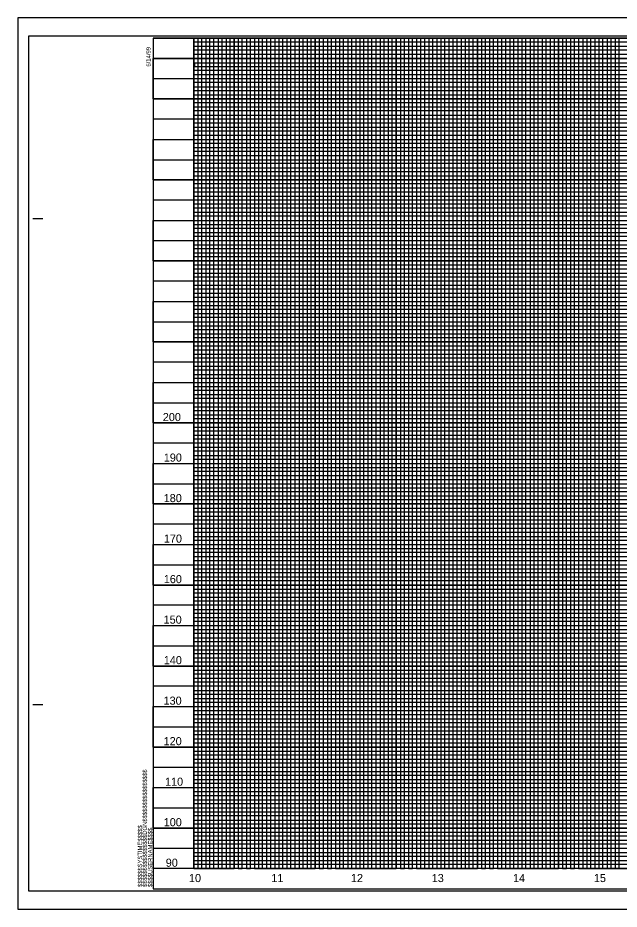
# Model space of a CAD drawing. Extents: x 1728093 to 1729777, y 538013 to 539113.
# Drawn here: x 1728093 to 1728835, y 538013 to 539113 of the extents above; entities that cross this region are included whole.
import ezdxf

# ---------------------------------------------------------------- set-up
doc = ezdxf.new("R2010")
doc.units = 0
for name, color, linetype in [('Exist Vertical Profile Horizontal Axis Label Minor', 7, 'Continuous'), ('Exist Vertical Profile Vertical Axis Label', 7, 'Continuous'), ('Scratch_Level_0', 7, 'Continuous'), ('Sheet Cutting Line CELL', 7, 'Continuous'), ('Sheet DOT Grid CELL', 7, 'Continuous'), ('Sheet Plot Border Inside CELL', 7, 'Continuous'), ('Sheet Plot Border Outside CELL', 7, 'Continuous'), ('Sheet Profile CELL', 7, 'Continuous'), ('Sheet Profile Grid Major CELL', 7, 'Continuous'), ('Sheet Profile Grid Middle CELL', 7, 'Continuous'), ('Sheet Profile Grid Minor CELL', 7, 'Continuous')]:
    doc.layers.add(name, color=color, linetype=linetype)

msp = doc.modelspace()

# ---------------------------------------------------------------- linework, layer by layer
at = {"layer": 'Scratch_Level_0'}
msp.add_lwpolyline([(1728309.9, 539088), (1729709.9, 539088), (1729709.9, 538063), (1728309.9, 538063)], close=True, dxfattribs=at)
at = {"layer": 'Sheet Cutting Line CELL'}
for p, q in [((1729776.9, 539113), (1728092.9, 539113)), ((1728092.9, 539113), (1728092.9, 538013)), ((1728092.9, 538013), (1729776.9, 538013))]:
    msp.add_line(p, q, dxfattribs=at)
at = {"layer": 'Sheet DOT Grid CELL'}
for p, q in [((1728309.9, 539088), (1728309.9, 538063)), ((1728359.9, 539088), (1728359.9, 538063)), ((1728409.9, 539088), (1728409.9, 538063)), ((1728459.9, 539088), (1728459.9, 538063)), ((1728509.9, 539088), (1728509.9, 538063)), ((1728559.9, 539088), (1728559.9, 538063)), ((1728609.9, 539088), (1728609.9, 538063)), ((1728659.9, 539088), (1728659.9, 538063)), ((1728709.9, 539088), (1728709.9, 538063)), ((1728759.9, 539088), (1728759.9, 538063)), ((1728809.9, 539088), (1728809.9, 538063)), ((1728259.9, 539063), (1729559.8, 539063)), ((1728259.9, 539013), (1729559.8, 539013)), ((1728259.9, 538963), (1729559.8, 538963)), ((1728259.9, 538913), (1729759.9, 538913)), ((1728259.9, 538863), (1729759.9, 538863)), ((1728259.9, 538813), (1729759.9, 538813)), ((1728259.9, 538763), (1729759.9, 538763)), ((1728259.9, 538713), (1729759.9, 538713)), ((1728259.9, 538613), (1729759.9, 538613)), ((1728259.9, 538563), (1729759.9, 538563)), ((1728259.9, 538513), (1729759.9, 538513)), ((1728259.9, 538463), (1729759.9, 538463)), ((1728259.9, 538413), (1729759.9, 538413)), ((1728259.9, 538363), (1729759.9, 538363)), ((1728259.9, 538313), (1729759.9, 538313)), ((1728259.9, 538263), (1729759.9, 538263)), ((1728259.9, 538213), (1729759.9, 538213)), ((1728259.9, 538163), (1729759.9, 538163)), ((1728259.9, 538113), (1729759.9, 538113))]:
    msp.add_line(p, q, dxfattribs=at)
at = {"layer": 'Sheet Plot Border Inside CELL'}
msp.add_lwpolyline([(1729772.4, 539090.5), (1728105.9, 539090.5), (1728105.9, 538035.4), (1729772.4, 538035.4)], close=True, dxfattribs=at)
at = {"layer": 'Sheet Plot Border Outside CELL'}
msp.add_lwpolyline([(1729776.9, 539113), (1728092.9, 539113), (1728092.9, 538013), (1729776.9, 538013)], close=True, dxfattribs=at)
at = {"layer": 'Sheet Profile CELL'}
for p, q in [((1728111.4, 538865.5), (1728123.9, 538865.5)), ((1728111.4, 538265.5), (1728123.9, 538265.5)), ((1729759.9, 538063), (1728259.9, 538063)), ((1728259.9, 538038), (1728259.9, 538038)), ((1728259.9, 538038), (1728259.9, 538038)), ((1728259.9, 538038), (1728259.9, 538038)), ((1728259.9, 538038), (1728259.9, 538038)), ((1728259.9, 538038), (1728259.9, 538038)), ((1728259.9, 538038), (1728259.9, 538038))]:
    msp.add_line(p, q, dxfattribs=at)
msp.add_lwpolyline([(1729759.9, 539088), (1728259.9, 539088), (1728259.9, 538038), (1729759.9, 538038)], close=True, dxfattribs=at)
msp.add_lwpolyline([(1728297.4, 538038), (1728297.4, 538038)], dxfattribs=at)
at = {"layer": 'Sheet Profile Grid Major CELL'}
for points in [[(1728259.9, 539088), (1728309.9, 539088), (1728309.9, 538063), (1728359.9, 538063), (1728359.9, 539088), (1728409.9, 539088), (1728409.9, 538063), (1728459.9, 538063), (1728459.9, 539088), (1728509.9, 539088), (1728509.9, 538063), (1728559.9, 538063), (1728559.9, 539088), (1728609.9, 539088), (1728609.9, 538063), (1728659.9, 538063), (1728659.9, 539088), (1728709.9, 539088), (1728709.9, 538063), (1728759.9, 538063), (1728759.9, 539088), (1728809.9, 539088), (1728809.9, 538063), (1728859.9, 538063)], [(1729559.8, 539013), (1728260, 539013), (1728260, 539062.9), (1729559.8, 539062.9)], [(1729759.9, 538913), (1728259.9, 538913), (1728259.9, 538963), (1729559.8, 538963)], [(1729759.9, 538813), (1728259.9, 538813), (1728259.9, 538863), (1729759.9, 538863)], [(1729759.9, 538713), (1728259.9, 538713), (1728259.9, 538763), (1729759.9, 538763)], [(1729759.9, 538613), (1728259.9, 538613), (1728259.9, 538663), (1729759.9, 538663)], [(1729759.9, 538513), (1728259.9, 538513), (1728259.9, 538563), (1729759.9, 538563)], [(1729759.9, 538413), (1728259.9, 538413), (1728259.9, 538463), (1729759.9, 538463)], [(1729759.9, 538313), (1728259.9, 538313), (1728259.9, 538363), (1729759.9, 538363)], [(1729759.9, 538213), (1728259.9, 538213), (1728259.9, 538263), (1729759.9, 538263)], [(1729759.9, 538113), (1728259.9, 538113), (1728259.9, 538163), (1729759.9, 538163)]]:
    msp.add_lwpolyline(points, dxfattribs=at)
at = {"layer": 'Sheet Profile Grid Middle CELL'}
for points in [[(1728334.9, 538063), (1728334.9, 539088), (1728384.9, 539088), (1728384.9, 538063), (1728434.9, 538063), (1728434.9, 539088), (1728484.9, 539088), (1728484.9, 538063), (1728534.9, 538063), (1728534.9, 539088), (1728584.9, 539088), (1728584.9, 538063), (1728634.9, 538063), (1728634.9, 539088), (1728684.9, 539088), (1728684.9, 538063), (1728734.9, 538063), (1728734.9, 539088), (1728784.9, 539088), (1728784.9, 538063), (1728834.9, 538063), (1728834.9, 539088), (1728884.9, 539088)], [(1728259.9, 539038), (1729559.8, 539038)], [(1729559.8, 538988), (1728259.9, 538988), (1728259.9, 538937.9), (1729559.8, 538937.9)], [(1729599.9, 538888), (1728259.9, 538888), (1728259.9, 538838), (1729759.9, 538838)], [(1729759.9, 538788), (1728259.9, 538788), (1728259.9, 538738), (1729759.9, 538738)], [(1729759.9, 538688), (1728259.9, 538688), (1728259.9, 538638), (1729759.9, 538638)], [(1729759.9, 538588), (1728259.9, 538588), (1728259.9, 538538), (1729759.9, 538538)], [(1729759.9, 538488), (1728259.9, 538488), (1728259.9, 538438), (1729759.9, 538438)], [(1729759.9, 538388), (1728259.9, 538388), (1728259.9, 538338), (1729759.9, 538338)], [(1729759.9, 538288), (1728259.9, 538288), (1728259.9, 538238), (1729759.9, 538238)], [(1729759.9, 538188), (1728259.9, 538188), (1728259.9, 538138), (1729759.9, 538138)], [(1729759.9, 538088), (1728259.9, 538088)]]:
    msp.add_lwpolyline(points, dxfattribs=at)
at = {"layer": 'Sheet Profile Grid Minor CELL'}
for p, q in [((1729709.9, 538923), (1728309.9, 538923)), ((1728309.9, 538923), (1728309.9, 538918)), ((1728309.9, 538918), (1729709.9, 538918)), ((1729709.9, 538908), (1728309.9, 538908)), ((1728309.9, 538908), (1728309.9, 538903)), ((1728309.9, 538903), (1729599.9, 538903)), ((1729599.9, 538883), (1728309.9, 538883)), ((1729709.9, 538853), (1728309.9, 538853)), ((1728309.9, 538853), (1728309.9, 538848)), ((1728309.9, 538848), (1729709.9, 538848))]:
    msp.add_line(p, q, dxfattribs=at)
for points in [[(1728314.9, 539088), (1728319.9, 539088), (1728324.9, 539088), (1728329.9, 539088), (1728339.9, 539088), (1728306.8, 539088), (1728311.8, 539088), (1728269.9, 539088), (1728274.9, 539088), (1728279.9, 539088), (1728289.9, 539088), (1728294.9, 539088), (1728299.9, 539088), (1728304.9, 539088), (1728314.9, 539088), (1728314.9, 538063), (1728319.9, 538063), (1728319.9, 539088), (1728324.9, 539088), (1728324.9, 538063), (1728329.9, 538063), (1728329.9, 539088), (1728339.9, 539088), (1728339.9, 538063), (1728344.9, 538063), (1728344.9, 539088), (1728349.9, 539088), (1728349.9, 538063), (1728354.9, 538063), (1728354.9, 539088), (1728364.9, 539088), (1728364.9, 538063), (1728369.9, 538063), (1728369.9, 539088), (1728374.9, 539088), (1728374.9, 538063), (1728379.9, 538063), (1728379.9, 539088), (1728389.9, 539088), (1728389.9, 538063), (1728394.9, 538063), (1728394.9, 539088), (1728399.9, 539088), (1728399.9, 538063), (1728404.9, 538063), (1728404.9, 539088), (1728414.9, 539088), (1728414.9, 538063), (1728419.9, 538063), (1728419.9, 539088), (1728424.9, 539088), (1728424.9, 538063), (1728429.9, 538063), (1728429.9, 539088), (1728439.9, 539088), (1728439.9, 538063), (1728444.9, 538063), (1728444.9, 539088), (1728449.9, 539088), (1728449.9, 538063), (1728454.9, 538063), (1728454.9, 539088), (1728464.9, 539088), (1728464.9, 538063), (1728469.9, 538063), (1728469.9, 539088), (1728474.9, 539088), (1728474.9, 538063)], [(1729559.8, 539083), (1728309.9, 539083), (1728309.9, 539078), (1729559.8, 539078)], [(1728474.9, 538063), (1728479.9, 538063), (1728479.9, 539088), (1728489.9, 539088), (1728489.9, 538063), (1728494.9, 538063), (1728494.9, 539088), (1728499.9, 539088), (1728499.9, 538063), (1728504.9, 538063), (1728504.9, 539088), (1728514.9, 539088), (1728514.9, 538063), (1728519.9, 538063), (1728519.9, 539088), (1728519.9, 539088), (1728524.9, 539088), (1728524.9, 538063), (1728529.9, 538063), (1728529.9, 539088), (1728539.9, 539088), (1728539.9, 538063), (1728544.9, 538063), (1728544.9, 539088), (1728549.9, 539088), (1728549.9, 538063), (1728554.9, 538063), (1728554.9, 539088), (1728564.9, 539088), (1728564.9, 538063), (1728569.9, 538063), (1728569.9, 539088), (1728574.9, 539088), (1728574.9, 538063), (1728579.9, 538063), (1728579.9, 539088), (1728589.9, 539088), (1728589.9, 538063), (1728594.9, 538063), (1728594.9, 539088), (1728599.9, 539088), (1728599.9, 538063), (1728604.9, 538063), (1728604.9, 539088), (1728614.9, 539088), (1728614.9, 538063), (1728619.9, 538063), (1728619.9, 539088), (1728624.9, 539088), (1728624.9, 538063), (1728629.9, 538063), (1728629.9, 539088), (1728639.9, 539088), (1728639.9, 538063), (1728654.9, 538063), (1728654.9, 539088), (1728664.9, 539088), (1728664.9, 538063), (1728669.9, 538063), (1728669.9, 539088), (1728674.9, 539088), (1728674.9, 538063), (1728679.9, 538063), (1728679.9, 539088), (1728689.9, 539088), (1728689.9, 538063), (1728694.9, 538063), (1728694.9, 539088), (1728699.9, 539088), (1728699.9, 538063), (1728704.9, 538063), (1728704.9, 539088), (1728714.9, 539088), (1728714.9, 538063), (1728719.9, 538063), (1728719.9, 539088), (1728724.9, 539088), (1728724.9, 538063), (1728729.9, 538063), (1728729.9, 539088), (1728739.9, 539088), (1728739.9, 538063), (1728744.9, 538063), (1728744.9, 539088), (1728749.9, 539088), (1728749.9, 538063), (1728754.9, 538063), (1728754.9, 539088), (1728764.9, 539088), (1728764.9, 538063), (1728769.9, 538063), (1728769.9, 539088), (1728774.9, 539088), (1728774.9, 538063), (1728779.9, 538063), (1728779.9, 539088), (1728789.9, 539088), (1728789.9, 538063)], [(1728644.9, 539088), (1728644.9, 538063), (1728649.9, 538063), (1728649.9, 539088)], [(1728644.9, 539087.4), (1728644.9, 538063), (1728649.9, 538063), (1728649.9, 539087.4)], [(1728794.9, 539088), (1728794.9, 538063), (1728799.9, 538063), (1728799.9, 539088), (1728804.9, 539088), (1728804.9, 538063), (1728814.9, 538063), (1728814.9, 539088), (1728819.9, 539088), (1728819.9, 538063), (1728824.9, 538063), (1728824.9, 539088), (1728829.9, 539088), (1728829.9, 538063)], [(1729559.8, 539073), (1728309.9, 539073), (1728309.9, 539068), (1729559.8, 539068)], [(1729559.8, 539057.2), (1728310.9, 539057.2), (1728310.9, 539053), (1729559.8, 539053)], [(1729559.8, 539048), (1728309.9, 539048), (1728309.9, 539043), (1729559.8, 539043)], [(1729559.8, 539033), (1728309.9, 539033), (1728309.9, 539028), (1729559.8, 539028)], [(1729559.8, 539023), (1728309.9, 539023), (1728309.9, 539018), (1729559.8, 539018)], [(1729559.8, 539008), (1728309.9, 539008), (1728309.9, 539003), (1729559.8, 539003)], [(1729559.8, 538998), (1728309.9, 538998), (1728309.9, 538993), (1729559.8, 538993)], [(1729559.8, 538983), (1728309.9, 538983), (1728309.9, 538978), (1729559.8, 538978)], [(1729559.8, 538973), (1728309.9, 538973), (1728309.9, 538968), (1729559.8, 538968)], [(1729559.8, 538958), (1728309.9, 538958), (1728309.9, 538953), (1729559.8, 538953)], [(1729559.8, 538948), (1728309.9, 538948), (1728309.9, 538948), (1728309.9, 538928), (1729559.8, 538928)], [(1728309.9, 538943), (1729559.8, 538943)], [(1729559.8, 538933), (1728309.9, 538933)], [(1729599.9, 538898), (1728309.9, 538898), (1728309.9, 538893), (1729599.9, 538893)], [(1729599.9, 538878), (1728309.9, 538878), (1728309.9, 538873), (1729599.9, 538873)], [(1729709.9, 538868), (1728309.9, 538868)], [(1728309.9, 538858), (1729709.9, 538858)], [(1729709.9, 538843), (1728309.9, 538843), (1728309.9, 538833), (1729709.9, 538833)], [(1729709.9, 538828), (1728309.9, 538828), (1728309.9, 538823), (1729709.9, 538823)], [(1729709.9, 538818), (1728309.9, 538818), (1728309.9, 538808), (1729709.9, 538808)], [(1729709.9, 538803), (1728309.9, 538803), (1728309.9, 538798), (1729709.9, 538798)], [(1729709.9, 538793), (1728309.9, 538793), (1728309.9, 538783), (1729709.9, 538783)], [(1729709.9, 538778), (1728309.9, 538778), (1728309.9, 538773), (1729709.9, 538773)], [(1729709.9, 538768), (1728309.9, 538768), (1728309.9, 538758), (1729709.9, 538758)], [(1729709.9, 538753), (1728309.9, 538753), (1728309.9, 538748), (1729709.9, 538748)], [(1729709.9, 538743), (1728309.9, 538743), (1728309.9, 538733), (1729709.9, 538733)], [(1729709.9, 538728), (1728309.9, 538728), (1728309.9, 538723), (1729709.9, 538723)], [(1729709.9, 538718), (1728309.9, 538718), (1728309.9, 538708), (1729709.9, 538708)], [(1729709.9, 538703), (1728309.9, 538703), (1728309.9, 538698), (1729709.9, 538698)], [(1729709.9, 538693), (1728309.9, 538693), (1728309.9, 538683), (1729709.9, 538683)], [(1729709.9, 538678), (1728309.9, 538678), (1728309.9, 538673), (1729709.9, 538673)], [(1729709.9, 538668), (1728309.9, 538668), (1728309.9, 538658), (1729709.9, 538658)], [(1729709.9, 538653), (1728309.9, 538653), (1728309.9, 538648), (1729709.9, 538648)], [(1729709.9, 538643), (1728309.9, 538643), (1728309.9, 538633), (1729709.9, 538633)], [(1729709.9, 538628), (1728309.9, 538628), (1728309.9, 538623), (1729709.9, 538623)], [(1729709.9, 538618), (1728309.9, 538618), (1728309.9, 538608), (1729709.9, 538608)], [(1729709.9, 538603), (1728309.9, 538603), (1728309.9, 538598), (1729709.9, 538598)], [(1729709.9, 538593), (1728309.9, 538593), (1728309.9, 538583), (1729709.9, 538583)], [(1729709.9, 538578), (1728309.9, 538578), (1728309.9, 538573), (1729709.9, 538573)], [(1729709.9, 538568), (1728309.9, 538568)], [(1728309.9, 538558), (1729709.9, 538558)], [(1729709.9, 538553), (1728309.9, 538553), (1728309.9, 538548), (1729709.9, 538548)], [(1729709.9, 538543), (1728309.9, 538543), (1728309.9, 538533), (1729709.9, 538533)], [(1729709.9, 538528), (1728309.9, 538528), (1728309.9, 538523), (1729709.9, 538523)], [(1729709.9, 538518), (1728309.9, 538518), (1728309.9, 538508), (1729709.9, 538508)], [(1729709.9, 538503), (1728309.9, 538503), (1728309.9, 538498), (1729709.9, 538498)], [(1729709.9, 538493), (1728309.9, 538493), (1728309.9, 538483), (1729709.9, 538483)], [(1729709.9, 538478), (1728309.9, 538478), (1728309.9, 538473), (1729709.9, 538473)], [(1729709.9, 538468), (1728309.9, 538468), (1728309.9, 538458), (1729709.9, 538458)], [(1729709.9, 538453), (1728309.9, 538453), (1728309.9, 538448), (1729709.9, 538448)], [(1729709.9, 538443), (1728309.9, 538443), (1728309.9, 538433), (1729709.9, 538433)], [(1729709.9, 538428), (1728309.9, 538428), (1728309.9, 538423), (1729709.9, 538423)], [(1729709.9, 538418), (1728309.9, 538418), (1728309.9, 538408), (1729709.9, 538408)], [(1729709.9, 538403), (1728309.9, 538403), (1728309.9, 538398), (1729709.9, 538398)], [(1729709.9, 538393), (1728309.9, 538393), (1728309.9, 538383), (1729709.9, 538383)], [(1729709.9, 538378), (1728309.9, 538378), (1728309.9, 538373), (1729709.9, 538373)], [(1729709.9, 538368), (1728309.9, 538368), (1728309.9, 538358), (1729709.9, 538358)], [(1729709.9, 538353), (1728309.9, 538353), (1728309.9, 538348), (1729709.9, 538348)], [(1729709.9, 538343), (1728309.9, 538343), (1728309.9, 538333), (1729709.9, 538333)], [(1729709.9, 538328), (1728309.9, 538328), (1728309.9, 538323), (1729709.9, 538323)], [(1729709.9, 538318), (1728309.9, 538318), (1728309.9, 538308), (1729709.9, 538308)], [(1729709.9, 538303), (1728309.9, 538303), (1728309.9, 538298), (1729709.9, 538298)], [(1729709.9, 538293), (1728309.9, 538293), (1728309.9, 538283), (1729709.9, 538283)], [(1729709.9, 538278), (1728309.9, 538278), (1728309.9, 538273), (1729709.9, 538273)], [(1729709.9, 538268), (1728309.9, 538268)], [(1728309.9, 538258), (1729709.9, 538258)], [(1729709.9, 538253), (1728309.9, 538253), (1728309.9, 538248), (1729709.9, 538248)], [(1729709.9, 538243), (1728309.9, 538243)], [(1728309.9, 538233), (1729709.9, 538233)], [(1729709.9, 538228), (1728309.9, 538228), (1728309.9, 538223), (1729709.9, 538223)], [(1729709.9, 538218), (1728309.9, 538218), (1728309.9, 538208), (1729709.9, 538208)], [(1729709.9, 538203), (1728309.9, 538203), (1728309.9, 538198), (1729709.9, 538198)], [(1729709.9, 538193), (1728309.9, 538193), (1728309.9, 538183), (1729709.9, 538183)], [(1729709.9, 538178), (1728309.9, 538178), (1728309.9, 538173), (1729709.9, 538173)], [(1729709.9, 538168), (1728309.9, 538168), (1728309.9, 538158), (1729709.9, 538158)], [(1729709.9, 538153), (1728309.9, 538153), (1728309.9, 538148), (1729709.9, 538148)], [(1729709.9, 538143), (1728309.9, 538143), (1728309.9, 538133), (1729709.9, 538133)], [(1729709.9, 538128), (1728309.9, 538128), (1728309.9, 538123), (1729709.9, 538123)], [(1729709.9, 538118), (1728309.9, 538118), (1728309.9, 538108), (1729709.9, 538108)], [(1729709.9, 538103), (1728309.9, 538103), (1728309.9, 538098), (1729709.9, 538098)], [(1729709.9, 538093), (1728309.9, 538093), (1728309.9, 538083), (1729709.9, 538083)], [(1729709.9, 538078), (1728309.9, 538078), (1728309.9, 538073), (1729709.9, 538073)], [(1729709.9, 538068), (1728309.9, 538068)]]:
    msp.add_lwpolyline(points, dxfattribs=at)

# ---------------------------------------------------------------- texts
at = {"layer": 'Exist Vertical Profile Horizontal Axis Label Minor'}
for s, p in [('10', (1728304.1, 538046.4)), ('11', (1728405.7, 538046.4)), ('12', (1728503.9, 538046.4)), ('13', (1728603.6, 538046.4)), ('14', (1728703.9, 538046.4)), ('15', (1728803.7, 538046.4))]:
    msp.add_text(s, height=10, dxfattribs=at).set_placement(p)
at = {"layer": 'Exist Vertical Profile Vertical Axis Label'}
for s, p in [('200', (1728271.8, 538615.3)), ('190', (1728273, 538565.3)), ('180', (1728272.9, 538515.3)), ('170', (1728273.1, 538465.3)), ('160', (1728273, 538415.3)), ('150', (1728272.8, 538365.3)), ('140', (1728273, 538315.3)), ('130', (1728272.7, 538265.3)), ('120', (1728272.8, 538215.3)), ('110', (1728274.5, 538165.3)), ('100', (1728272.9, 538115.3)), ('90', (1728275.4, 538065.3))]:
    msp.add_text(s, height=10, dxfattribs=at).set_placement(p)
at = {"layer": 'Sheet Profile CELL'}
for s, p in [('5/14/99', (1728256.6, 539052.8)), ('$$$$$$$$$$$$$$$$DGN$$$$$$$$$$$$$$$$', (1728252.2, 538040.3)), ('$$$$$$SYSTIME$$$$$', (1728246.2, 538040.3)), ('$$$$USERNAME$$$$', (1728258.8, 538040.3))]:
    msp.add_text(s, height=5.25, rotation=90, dxfattribs=at).set_placement(p)

doc.saveas('drawing.dxf')
